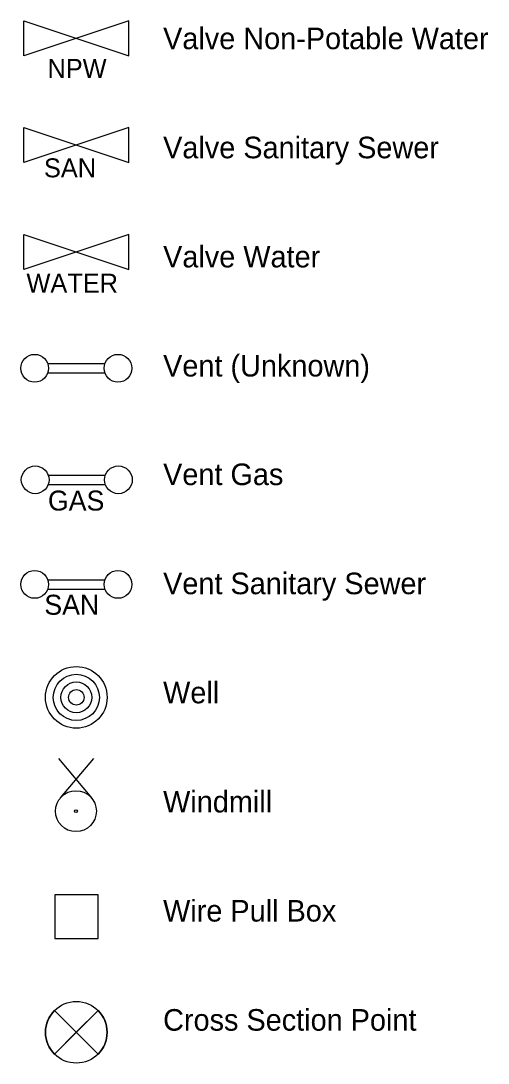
# Model space of a CAD drawing. Extents: x -371 to 730, y -9 to 425.
# Drawn here: x 68.1 to 106, y 332.1 to 416.6 of the extents above; entities that cross this region are included whole.
import ezdxf

# ---------------------------------------------------------------- set-up
doc = ezdxf.new("R2010")
doc.units = 0
for name, color, linetype in [('PullBox_ep', 7, 'Continuous'), ('ValveSewer_ep', 7, 'Continuous'), ('ValveWater_ep', 7, 'Continuous'), ('ValveWaterNP_ep', 7, 'Continuous'), ('Vent_ep', 7, 'Continuous'), ('VentGas_ep', 7, 'Continuous'), ('VentSewer_ep', 7, 'Continuous'), ('Wells_ep', 7, 'Continuous'), ('WindMill_ep', 7, 'Continuous'), ('XSPt_ep', 7, 'Continuous')]:
    doc.layers.add(name, color=color, linetype=linetype)

msp = doc.modelspace()

# ---------------------------------------------------------------- linework, layer by layer
at = {"layer": 'PullBox_ep'}
for p, q in [((74.381, 345.713), (70.846, 345.713)), ((70.846, 345.713), (70.846, 342.178)), ((74.381, 342.178), (74.381, 345.713)), ((70.846, 342.178), (74.381, 342.178))]:
    msp.add_line(p, q, dxfattribs=at)
at = {"layer": 'ValveSewer_ep'}
for p, q in [((68.331, 405.096), (68.331, 407.942)), ((68.331, 407.942), (76.869, 405.096)), ((76.869, 407.942), (68.331, 405.096)), ((76.869, 405.096), (76.869, 407.942))]:
    msp.add_line(p, q, dxfattribs=at)
at = {"layer": 'ValveWater_ep'}
for p, q in [((68.331, 396.432), (68.331, 399.278)), ((68.331, 399.278), (76.869, 396.432)), ((76.869, 399.278), (68.331, 396.432)), ((76.869, 396.432), (76.869, 399.278))]:
    msp.add_line(p, q, dxfattribs=at)
at = {"layer": 'ValveWaterNP_ep'}
for p, q in [((68.331, 413.752), (68.331, 416.598)), ((68.331, 416.598), (76.869, 413.752)), ((76.869, 416.598), (68.331, 413.752)), ((76.869, 413.752), (76.869, 416.598))]:
    msp.add_line(p, q, dxfattribs=at)
at = {"layer": 'Vent_ep'}
for p, q in [((70.285, 388.798), (74.914, 388.798)), ((70.285, 388.048), (74.914, 388.048))]:
    msp.add_line(p, q, dxfattribs=at)
for centre in [(69.225, 388.423), (75.975, 388.423)]:
    msp.add_circle(centre, 1.125, dxfattribs=at)
at = {"layer": 'VentGas_ep'}
for p, q in [((70.325, 379.748), (74.954, 379.748)), ((70.325, 378.998), (74.954, 378.998))]:
    msp.add_line(p, q, dxfattribs=at)
for centre in [(69.264, 379.373), (76.014, 379.373)]:
    msp.add_circle(centre, 1.125, dxfattribs=at)
at = {"layer": 'VentSewer_ep'}
for p, q in [((70.285, 371.262), (74.914, 371.262)), ((70.285, 370.512), (74.914, 370.512))]:
    msp.add_line(p, q, dxfattribs=at)
for centre in [(69.225, 370.887), (75.975, 370.887)]:
    msp.add_circle(centre, 1.125, dxfattribs=at)
at = {"layer": 'Wells_ep'}
for radius in [2.5, 1.875, 1.25, 0.625]:
    msp.add_circle((72.6, 361.729), radius, dxfattribs=at)
at = {"layer": 'WindMill_ep'}
for p, q in [((71.143, 356.767), (73.836, 353.567)), ((73.989, 356.767), (71.296, 353.567))]:
    msp.add_line(p, q, dxfattribs=at)
for radius in [1.66, 0.119]:
    msp.add_circle((72.566, 352.498), radius, dxfattribs=at)
at = {"layer": 'XSPt_ep'}
for p, q in [((70.832, 336.329), (74.367, 332.793)), ((70.832, 332.793), (74.367, 336.329))]:
    msp.add_line(p, q, dxfattribs=at)
for points in [[(70.832, 332.793), (72.6, 334.561), (70.832, 336.329)], [(74.367, 336.329), (72.6, 334.561), (74.367, 332.793)]]:
    msp.add_lwpolyline(points, dxfattribs=at)
msp.add_circle((72.6, 334.561), 2.5, dxfattribs=at)
for start, end in [(135, 180), (0, 45), (180, 225), (315, 0)]:
    msp.add_arc((72.6, 334.561), 2.5, start, end, dxfattribs=at)

# ---------------------------------------------------------------- texts
for s, p in [('Valve Non-Potable Water', (79.639, 414.299)), ('Valve Sanitary Sewer', (79.639, 405.45)), ('Valve Water', (79.639, 396.6)), ('Vent (Unknown)', (79.639, 387.75)), ('Vent Gas', (79.639, 378.944)), ('Vent Sanitary Sewer', (79.639, 370.094)), ('Well', (79.639, 361.244)), ('Windmill', (79.639, 352.394)), ('Wire Pull Box', (79.639, 343.544)), ('Cross Section Point', (79.639, 334.694))]:
    msp.add_text(s, height=1.75).set_placement(p)
at = {"layer": 'ValveSewer_ep'}
msp.add_text('SAN', height=1.5369, dxfattribs=at).set_placement((69.974, 403.906))
at = {"layer": 'ValveWater_ep'}
msp.add_text('WATER', height=1.5369, dxfattribs=at).set_placement((68.558, 394.551))
at = {"layer": 'ValveWaterNP_ep'}
msp.add_text('NPW', height=1.5369, dxfattribs=at).set_placement((70.259, 411.974))
at = {"layer": 'VentGas_ep'}
msp.add_text('GAS', height=1.62, dxfattribs=at).set_placement((70.298, 376.88))
at = {"layer": 'VentSewer_ep'}
msp.add_text('SAN', height=1.62, dxfattribs=at).set_placement((70.005, 368.43))

doc.saveas('drawing.dxf')
